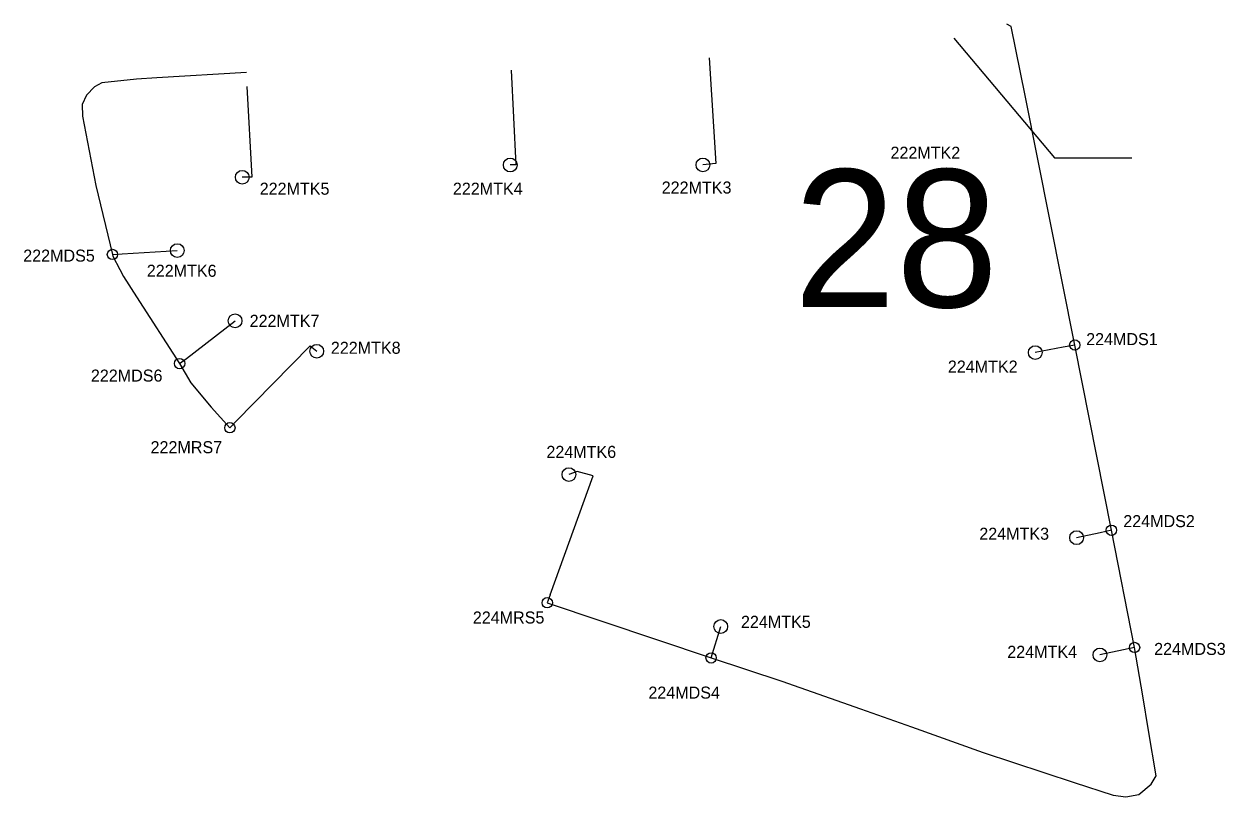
# Model space of a CAD drawing. Extents: x -835291 to -833547, y -1108367 to -1106510.
# Drawn here: x -834181 to -834006.4, y -1108172.2 to -1108059.9 of the extents above; entities that cross this region are included whole.
import ezdxf

# ---------------------------------------------------------------- set-up
doc = ezdxf.new("R2010")
doc.units = 0
for name, color, linetype in [('Vrstva 1', 7, 'Continuous'), ('Vrstva 18', 7, 'Continuous'), ('Vrstva 21', 7, 'Continuous'), ('Vrstva 3', 7, 'Continuous'), ('Vrstva 5', 7, 'Continuous')]:
    doc.layers.add(name, color=color, linetype=linetype)

msp = doc.modelspace()

# ---------------------------------------------------------------- linework, layer by layer
at = {"layer": 'Vrstva 1'}
for p, q in [((-834168.16, -1108093.37), (-834166.73, -1108093.27)), ((-834028.2, -1108106.53), (-834029.89, -1108106.83)), ((-834022.88, -1108133.47), (-834028.2, -1108106.53)), ((-834158.4, -1108109.24), (-834157.4, -1108108.51)), ((-834151.09, -1108118.56), (-834150.22, -1108117.65)), ((-834022.88, -1108133.47), (-834024.52, -1108133.82)), ((-834019.51, -1108150.5), (-834022.88, -1108133.47)), ((-834019.51, -1108150.5), (-834021.11, -1108150.87))]:
    msp.add_line(p, q, dxfattribs=at)
for points in [[(-834028.2, -1108106.53), (-834035.43, -1108070.27), (-834037.44, -1108060.22), (-834038.07, -1108059.87)], [(-834148.68, -1108066.93), (-834161.71, -1108067.69), (-834164.68, -1108067.88), (-834169.73, -1108068.4), (-834170.77, -1108068.98), (-834171.92, -1108070.23), (-834172.57, -1108071.57), (-834172.53, -1108073.24), (-834170.59, -1108083.34), (-834168.16, -1108093.37)], [(-834168.16, -1108093.37), (-834168.09, -1108093.63), (-834167.08, -1108095.57), (-834166.55, -1108096.58), (-834164.67, -1108099.52), (-834158.4, -1108109.24)], [(-834158.4, -1108109.24), (-834156.76, -1108112.03), (-834153.8, -1108115.55), (-834151.09, -1108118.56)], [(-834104.49, -1108142.84), (-834104.92, -1108144), (-834081.09, -1108152.03)], [(-834081.09, -1108152.03), (-834070.82, -1108155.38), (-834059.36, -1108159.4), (-834051.96, -1108162.04), (-834041.52, -1108165.76), (-834028.29, -1108170.14), (-834022.62, -1108171.99), (-834020.8, -1108172.24), (-834018.88, -1108171.9), (-834017.09, -1108170.36), (-834016.37, -1108169.16), (-834017.49, -1108162.57), (-834018.32, -1108157.55), (-834019.51, -1108150.5)]]:
    msp.add_lwpolyline(points, dxfattribs=at)
at = {"layer": 'Vrstva 21'}
for p, q in [((-834166.73, -1108093.27), (-834158.73, -1108092.8)), ((-834157.4, -1108108.51), (-834150.34, -1108103.02)), ((-834029.89, -1108106.83), (-834033.95, -1108107.64)), ((-834024.52, -1108133.82), (-834027.93, -1108134.54)), ((-834081.09, -1108152.03), (-834079.69, -1108147.46)), ((-834021.11, -1108150.87), (-834024.55, -1108151.59))]:
    msp.add_line(p, q, dxfattribs=at)
for points in [[(-834081.36, -1108064.8), (-834080.39, -1108080.14), (-834082.28, -1108080.35)], [(-834110.16, -1108066.57), (-834109.48, -1108080.33), (-834110.31, -1108080.36)], [(-834148.6, -1108068.97), (-834147.89, -1108082.14), (-834149.29, -1108082.14)], [(-834150.22, -1108117.65), (-834139.43, -1108106.64), (-834138.46, -1108107.44)], [(-834104.49, -1108142.84), (-834098.24, -1108125.54), (-834100.56, -1108124.93), (-834101.78, -1108125.37)]]:
    msp.add_lwpolyline(points, dxfattribs=at)
at = {"layer": 'Vrstva 3'}
for centre, radius in [((-834110.31, -1108080.36), 1), ((-834082.28, -1108080.35), 1), ((-834149.29, -1108082.14), 1), ((-834168.16, -1108093.37), 0.75), ((-834158.73, -1108092.8), 1), ((-834150.34, -1108103.02), 1), ((-834138.46, -1108107.44), 1), ((-834033.95, -1108107.64), 1), ((-834028.2, -1108106.53), 0.75), ((-834158.4, -1108109.24), 0.75), ((-834151.09, -1108118.56), 0.75), ((-834101.78, -1108125.37), 1), ((-834022.88, -1108133.47), 0.75), ((-834027.93, -1108134.54), 1), ((-834104.92, -1108144), 0.75), ((-834079.69, -1108147.46), 1), ((-834019.51, -1108150.5), 0.75), ((-834081.09, -1108152.03), 0.75), ((-834024.55, -1108151.59), 1)]:
    msp.add_circle(centre, radius, dxfattribs=at)
at = {"layer": 'Vrstva 5'}
msp.add_lwpolyline([(-834045.8, -1108061.93), (-834031.15, -1108079.33), (-834019.89, -1108079.33)], dxfattribs=at)

# ---------------------------------------------------------------- texts
at = {"layer": 'Vrstva 18'}
msp.add_text('28', height=20, dxfattribs=at).set_placement((-834069.09, -1108101.02))
at = {"layer": 'Vrstva 5'}
for s, p in [('222MTK2', (-834055.01, -1108079.45)), ('222MTK5', (-834146.75, -1108084.68)), ('222MTK4', (-834118.65, -1108084.68)), ('222MTK3', (-834088.28, -1108084.51)), ('222MDS5', (-834181.14, -1108094.41)), ('222MTK6', (-834163.17, -1108096.61)), ('222MTK7', (-834148.21, -1108103.89)), ('224MDS1', (-834026.55, -1108106.55)), ('222MTK8', (-834136.4, -1108107.81)), ('222MDS6', (-834171.3, -1108111.85)), ('224MTK2', (-834046.66, -1108110.54)), ('222MRS7', (-834162.62, -1108122.26)), ('224MTK6', (-834105.05, -1108122.94)), ('224MDS2', (-834021.15, -1108133.01)), ('224MTK3', (-834042.09, -1108134.84)), ('224MRS5', (-834115.75, -1108147.02)), ('224MTK5', (-834076.75, -1108147.65)), ('224MTK4', (-834038.02, -1108152.01)), ('224MDS3', (-834016.66, -1108151.59)), ('224MDS4', (-834090.22, -1108157.94))]:
    msp.add_text(s, height=1.75, dxfattribs=at).set_placement(p)

doc.saveas('drawing.dxf')
